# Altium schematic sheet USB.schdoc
size 245 x 68 mm
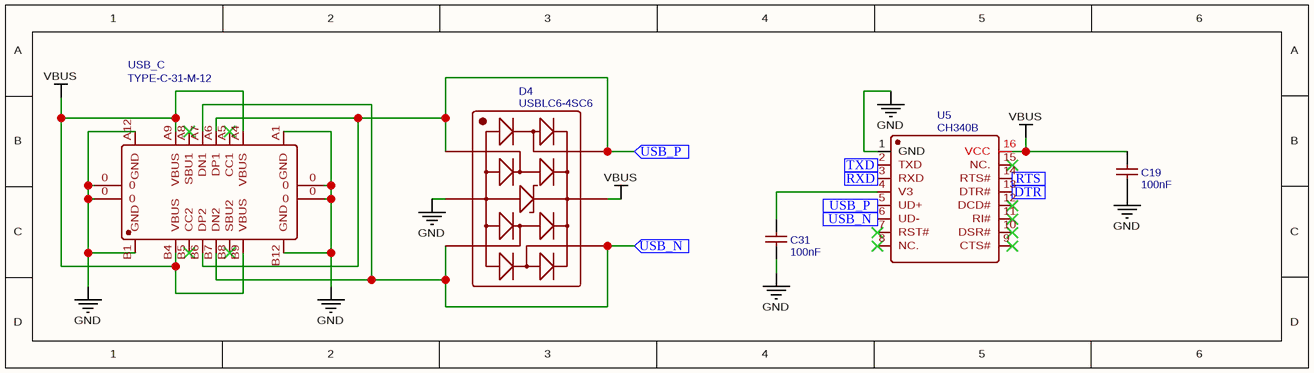
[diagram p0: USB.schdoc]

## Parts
C19  100nF  [C0805]
C31  100nF  [C0805]
D4  USBLC6-4SC6  [SOT-23-6_L2.9-W1.6-P0.95-LS2.8-BR]
U5  CH340B  [SOIC-16_L9.9-W3.9-P1.27-LS6.0-BL]
USB_C  TYPE-C-31-M-12  [USB-C_SMD-TYPE-C-31-M-12]

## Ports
DTR (in), RTS (in), RXD (in), TXD (in), USB_N (in), USB_P (in)

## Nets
GND: C19.2 C31.2 D4.2 U5.1(GND) USB_C.0 USB_C.A1(GND) USB_C.A12(GND) USB_C.B1(GND) USB_C.B12(GND)
VBUS: C19.1 D4.5 U5.16(VCC) USB_C.A4(VBUS) USB_C.A9(VBUS) USB_C.B4(VBUS) USB_C.B9(VBUS)
DTR: U5.13(DTR#) ; port DTR
RTS: U5.14(RTS#) ; port RTS
RXD: U5.3(RXD) ; port RXD
TXD: U5.2(TXD) ; port TXD
USB_N: D4.3 D4.4 U5.6(UD-) USB_C.A7(DN1) USB_C.B7(DN2) ; port USB_N
USB_P: D4.1 D4.6 U5.5(UD+) USB_C.A6(DP1) USB_C.B6(DP2) ; port USB_P
NetC31_1: C31.1 U5.4(V3)

Not connected (* = marked no-connect by the designer): U5 7(RST#)* 8(NC.)* 9(CTS#)* 10(DSR#)* 11(RI#)* 12(DCD#)* 15(NC.)*; USB_C A5(CC1)* A8(SBU1)* B5(CC2)* B8(SBU2)*

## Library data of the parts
C19 C31 = 100nF: BOM_Manufacturer Part: CC0805KRX7R9BB104; BOM_Manufacturer: YAGEO; nameAlias: Capacitance
D4 = USBLC6-4SC6: BOM_Manufacturer: STMicroelectronics
U5 = CH340B: BOM_Manufacturer: WCH
USB_C = TYPE-C-31-M-12: BOM_Manufacturer: Rectangular Connectors - Contacts; Contributor: LCSC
